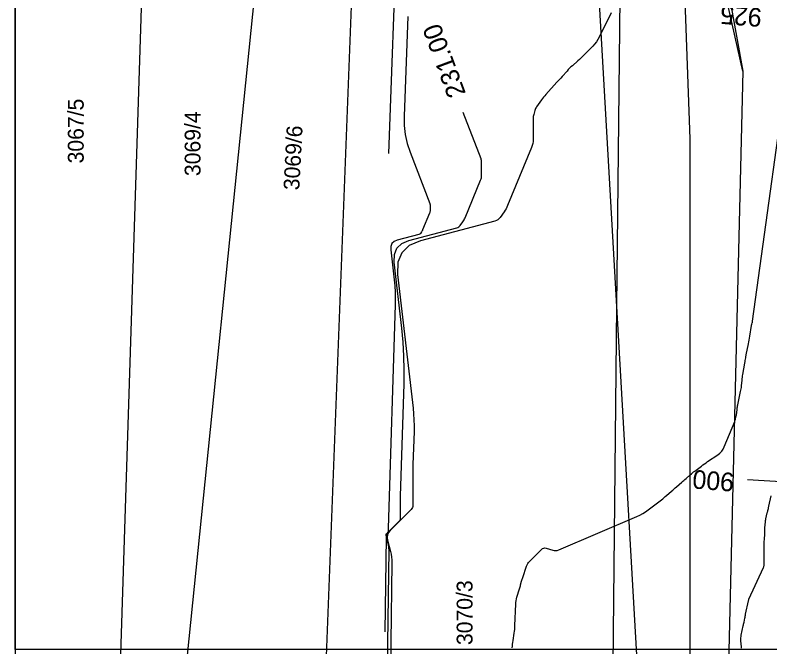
# Model space of a CAD drawing. Extents: x -534410 to -534262, y -1190162 to -1189584.
# Drawn here: x -534410.13 to -534369.58, y -1189689.33 to -1189655.39 of the extents above; entities that cross this region are included whole.
import ezdxf

# ---------------------------------------------------------------- set-up
doc = ezdxf.new("R2010")
doc.units = 0
for name, color, linetype in [('30', 7, 'Continuous'), ('31', 7, 'Continuous'), ('40', 7, 'Continuous'), ('_N_text', 7, 'Continuous'), ('_rámeček', 7, 'Continuous'), ('_rámeček_mřížka', 7, 'Continuous'), ('Hranice parcel', 7, 'Continuous'), ('Parcelní čísla', 7, 'Continuous')]:
    doc.layers.add(name, color=color, linetype=linetype)

msp = doc.modelspace()

# ---------------------------------------------------------------- linework, layer by layer
at = {"layer": '30'}
for points in [[(-534389.62, -1189650.598), (-534390.072, -1189662.819)], [(-534383.427, -1189689.383), (-534383.415, -1189689.283), (-534383.403, -1189689.183), (-534383.389, -1189689.084), (-534383.375, -1189688.984), (-534383.316, -1189688.586), (-534383.302, -1189688.487), (-534383.291, -1189688.387), (-534383.283, -1189688.287), (-534383.278, -1189688.186), (-534383.231, -1189687.038), (-534383.224, -1189686.942), (-534383.211, -1189686.847), (-534383.192, -1189686.752), (-534383.168, -1189686.659), (-534383.03, -1189686.202), (-534383.016, -1189686.152), (-534383.001, -1189686.101), (-534382.987, -1189686.051), (-534382.973, -1189686), (-534382.92, -1189685.797), (-534382.906, -1189685.746), (-534382.891, -1189685.695), (-534382.876, -1189685.645), (-534382.86, -1189685.595), (-534382.658, -1189684.99), (-534382.63, -1189684.92), (-534382.594, -1189684.854), (-534382.55, -1189684.794), (-534382.499, -1189684.739), (-534382.276, -1189684.528), (-534382.221, -1189684.475), (-534382.167, -1189684.421), (-534382.113, -1189684.367), (-534382.06, -1189684.311), (-534381.849, -1189684.089), (-534381.793, -1189684.043), (-534381.733, -1189684.017), (-534381.668, -1189684.011), (-534381.597, -1189684.024), (-534381.25, -1189684.135), (-534381.168, -1189684.153), (-534381.087, -1189684.157), (-534381.007, -1189684.146), (-534380.927, -1189684.119), (-534376.732, -1189682.324), (-534376.571, -1189682.249), (-534376.415, -1189682.164), (-534376.265, -1189682.07), (-534376.121, -1189681.967), (-534375.412, -1189681.425), (-534375.342, -1189681.371), (-534375.273, -1189681.315), (-534375.204, -1189681.257), (-534375.137, -1189681.199), (-534374.867, -1189680.961), (-534374.801, -1189680.903), (-534374.735, -1189680.845), (-534374.669, -1189680.787), (-534374.603, -1189680.729), (-534374.322, -1189680.483), (-534374.264, -1189680.432), (-534374.206, -1189680.382), (-534374.148, -1189680.331), (-534374.09, -1189680.281), (-534373.859, -1189680.079), (-534373.801, -1189680.029), (-534373.742, -1189679.98), (-534373.682, -1189679.932), (-534373.621, -1189679.885), (-534373.26, -1189679.611), (-534373.18, -1189679.55), (-534373.098, -1189679.491), (-534373.015, -1189679.432), (-534372.932, -1189679.375), (-534372.381, -1189679.005), (-534372.27, -1189678.918), (-534372.174, -1189678.818), (-534372.095, -1189678.704), (-534372.032, -1189678.578), (-534371.474, -1189677.214), (-534371.46, -1189677.178), (-534371.448, -1189677.142), (-534371.437, -1189677.106), (-534371.428, -1189677.068), (-534371.394, -1189676.919), (-534371.386, -1189676.882), (-534371.38, -1189676.844), (-534371.374, -1189676.806), (-534371.369, -1189676.769), (-534371.341, -1189676.534), (-534371.334, -1189676.482), (-534371.326, -1189676.43), (-534371.317, -1189676.379), (-534371.307, -1189676.328), (-534371.157, -1189675.615), (-534371.142, -1189675.539), (-534371.129, -1189675.462), (-534371.118, -1189675.385), (-534371.11, -1189675.308), (-534371.08, -1189674.999), (-534371.072, -1189674.922), (-534371.062, -1189674.845), (-534371.051, -1189674.768), (-534371.038, -1189674.692), (-534370.929, -1189674.091), (-534370.923, -1189674.054), (-534370.916, -1189674.017), (-534370.91, -1189673.98), (-534370.904, -1189673.942), (-534370.881, -1189673.793), (-534370.875, -1189673.756), (-534370.869, -1189673.718), (-534370.862, -1189673.681), (-534370.855, -1189673.644), (-534370.74, -1189673.05), (-534370.721, -1189672.947), (-534370.702, -1189672.844), (-534370.685, -1189672.741), (-534370.668, -1189672.638), (-534370.574, -1189672.057), (-534370.571, -1189672.038), (-534370.566, -1189672.02), (-534370.561, -1189672.002), (-534370.555, -1189671.984), (-534370.529, -1189671.912), (-534370.523, -1189671.894), (-534370.518, -1189671.876), (-534370.514, -1189671.857), (-534370.511, -1189671.838), (-534368.346, -1189656.186)], [(-534390.277, -1189701.721), (-534390.042, -1189684.12), (-534390.043, -1189684.036), (-534390.05, -1189683.951), (-534390.063, -1189683.868), (-534390.081, -1189683.785), (-534390.164, -1189683.455), (-534390.175, -1189683.375), (-534390.165, -1189683.301), (-534390.135, -1189683.232), (-534390.085, -1189683.169), (-534389.476, -1189682.56), (-534389.452, -1189682.531), (-534389.435, -1189682.5), (-534389.425, -1189682.466), (-534389.422, -1189682.43), (-534389.422, -1189682.277), (-534389.422, -1189682.201), (-534389.422, -1189682.125), (-534389.422, -1189681.932), (-534389.422, -1189681.826), (-534389.422, -1189681.651), (-534389.422, -1189681.545), (-534389.422, -1189681.387), (-534389.422, -1189681.349), (-534389.422, -1189681.311), (-534389.421, -1189681.273), (-534389.42, -1189681.235), (-534389.233, -1189675.203), (-534389.223, -1189674.453), (-534389.24, -1189673.705), (-534389.285, -1189672.958), (-534389.357, -1189672.212), (-534389.766, -1189668.662), (-534389.756, -1189668.243), (-534389.621, -1189667.91), (-534389.36, -1189667.662), (-534388.975, -1189667.5), (-534386.4, -1189666.813), (-534386.345, -1189666.793), (-534386.295, -1189666.765), (-534386.251, -1189666.729), (-534386.213, -1189666.684), (-534386.071, -1189666.489), (-534386.037, -1189666.439), (-534386.006, -1189666.387), (-534385.979, -1189666.334), (-534385.954, -1189666.279), (-534385.123, -1189664.258), (-534385.099, -1189664.191), (-534385.082, -1189664.123), (-534385.071, -1189664.053), (-534385.068, -1189663.982), (-534385.068, -1189663.597), (-534385.068, -1189663.463), (-534385.068, -1189663.284), (-534385.07, -1189663.239), (-534385.076, -1189663.195), (-534385.086, -1189663.152), (-534385.1, -1189663.11), (-534386.06, -1189660.617)]]:
    msp.add_lwpolyline(points, dxfattribs=at)
at = {"layer": '31'}
for points in [[(-534389.036, -1189655.461), (-534389.234, -1189660.821), (-534389.228, -1189661.315), (-534389.172, -1189661.802), (-534389.067, -1189662.28), (-534388.913, -1189662.749), (-534387.852, -1189665.506), (-534387.845, -1189665.525), (-534387.841, -1189665.544), (-534387.838, -1189665.564), (-534387.837, -1189665.584), (-534387.837, -1189665.745), (-534387.837, -1189665.898), (-534387.839, -1189665.93), (-534387.843, -1189665.962), (-534387.851, -1189665.992), (-534387.862, -1189666.023), (-534388.236, -1189666.932), (-534388.247, -1189666.957), (-534388.26, -1189666.981), (-534388.274, -1189667.004), (-534388.289, -1189667.027), (-534388.353, -1189667.115), (-534388.37, -1189667.135), (-534388.39, -1189667.151), (-534388.412, -1189667.164), (-534388.437, -1189667.173), (-534389.596, -1189667.482), (-534389.77, -1189667.555), (-534389.887, -1189667.667), (-534389.948, -1189667.817), (-534389.952, -1189668.005), (-534389.769, -1189669.604), (-534389.736, -1189669.94), (-534389.716, -1189670.276), (-534389.708, -1189670.613), (-534389.712, -1189670.951), (-534390.085, -1189682.943), (-534390.085, -1189682.962), (-534390.085, -1189683.066), (-534390.085, -1189683.119), (-534390.085, -1189683.144), (-534390.086, -1189683.15), (-534390.088, -1189683.156), (-534390.09, -1189683.161), (-534390.094, -1189683.166), (-534390.197, -1189683.269), (-534390.206, -1189683.28), (-534390.211, -1189683.291), (-534390.212, -1189683.304), (-534390.211, -1189683.317), (-534390.197, -1189683.373), (-534390.194, -1189683.387), (-534390.191, -1189683.401), (-534390.19, -1189683.415), (-534390.19, -1189683.43), (-534390.258, -1189688.509)], [(-534378.108, -1189655.268), (-534378.751, -1189656.572), (-534378.823, -1189656.705), (-534378.905, -1189656.83), (-534378.997, -1189656.948), (-534379.1, -1189657.059), (-534379.6, -1189657.56), (-534379.672, -1189657.631), (-534379.745, -1189657.701), (-534379.819, -1189657.77), (-534379.894, -1189657.838), (-534380.195, -1189658.107), (-534380.269, -1189658.176), (-534380.341, -1189658.246), (-534380.412, -1189658.319), (-534380.48, -1189658.393), (-534380.75, -1189658.694), (-534380.817, -1189658.769), (-534380.885, -1189658.844), (-534380.952, -1189658.92), (-534381.02, -1189658.995), (-534381.618, -1189659.659), (-534381.68, -1189659.73), (-534381.739, -1189659.802), (-534381.797, -1189659.875), (-534381.853, -1189659.95), (-534382.116, -1189660.313), (-534382.147, -1189660.36), (-534382.173, -1189660.41), (-534382.195, -1189660.461), (-534382.212, -1189660.515), (-534382.27, -1189660.735), (-534382.283, -1189660.79), (-534382.292, -1189660.845), (-534382.297, -1189660.902), (-534382.299, -1189660.958), (-534382.299, -1189661.331), (-534382.299, -1189661.47), (-534382.299, -1189661.539), (-534382.299, -1189662.067), (-534382.304, -1189662.177), (-534382.32, -1189662.284), (-534382.346, -1189662.39), (-534382.383, -1189662.494), (-534383.672, -1189665.626), (-534383.71, -1189665.711), (-534383.753, -1189665.793), (-534383.8, -1189665.873), (-534383.853, -1189665.95), (-534384.073, -1189666.254), (-534384.132, -1189666.323), (-534384.2, -1189666.379), (-534384.277, -1189666.423), (-534384.363, -1189666.453), (-534388.353, -1189667.518), (-534388.951, -1189667.769), (-534389.354, -1189668.153), (-534389.564, -1189668.67), (-534389.579, -1189669.318), (-534388.753, -1189676.5), (-534388.722, -1189676.816), (-534388.703, -1189677.132), (-534388.696, -1189677.448), (-534388.7, -1189677.765), (-534388.755, -1189679.527), (-534388.757, -1189679.597), (-534388.758, -1189679.667), (-534388.759, -1189679.736), (-534388.759, -1189679.806), (-534388.759, -1189680.095), (-534388.759, -1189680.224), (-534388.759, -1189680.353), (-534388.759, -1189680.61), (-534388.759, -1189680.739), (-534388.759, -1189680.868), (-534388.759, -1189681.157), (-534388.759, -1189681.227), (-534388.759, -1189681.297), (-534388.759, -1189681.366), (-534388.759, -1189681.436), (-534388.759, -1189681.715), (-534388.765, -1189681.782), (-534388.783, -1189681.844), (-534388.814, -1189681.901), (-534388.857, -1189681.953), (-534389.973, -1189683.069), (-534390.065, -1189683.184), (-534390.12, -1189683.31), (-534390.137, -1189683.446), (-534390.118, -1189683.592), (-534389.965, -1189684.197), (-534389.932, -1189684.348), (-534389.909, -1189684.501), (-534389.896, -1189684.656), (-534389.893, -1189684.811), (-534389.95, -1189689.079), (-534389.953, -1189689.842)], [(-534371.113, -1189689.402), (-534371.118, -1189689.322), (-534371.142, -1189689.004), (-534371.145, -1189688.924), (-534371.143, -1189688.845), (-534371.135, -1189688.767), (-534371.121, -1189688.688), (-534371.018, -1189688.202), (-534371.007, -1189688.149), (-534370.996, -1189688.097), (-534370.985, -1189688.045), (-534370.974, -1189687.992), (-534370.931, -1189687.782), (-534370.921, -1189687.73), (-534370.91, -1189687.678), (-534370.899, -1189687.625), (-534370.887, -1189687.573), (-534370.734, -1189686.861), (-534370.73, -1189686.844), (-534370.727, -1189686.828), (-534370.72, -1189686.794), (-534370.719, -1189686.785), (-534370.716, -1189686.777), (-534370.713, -1189686.769), (-534370.71, -1189686.761), (-534369.927, -1189685.056), (-534369.915, -1189685.024), (-534369.906, -1189684.991), (-534369.9, -1189684.958), (-534369.898, -1189684.923), (-534369.898, -1189684.68), (-534369.898, -1189684.075), (-534369.898, -1189683.971), (-534369.898, -1189683.832), (-534369.898, -1189683.797), (-534369.897, -1189683.762), (-534369.894, -1189683.727), (-534369.891, -1189683.693), (-534369.875, -1189683.53), (-534369.871, -1189683.491), (-534369.869, -1189683.452), (-534369.867, -1189683.414), (-534369.865, -1189683.375), (-534369.854, -1189682.937), (-534369.853, -1189682.896), (-534369.85, -1189682.856), (-534369.847, -1189682.815), (-534369.843, -1189682.774), (-534369.823, -1189682.612), (-534369.818, -1189682.572), (-534369.812, -1189682.532), (-534369.804, -1189682.491), (-534369.796, -1189682.452), (-534369.722, -1189682.123), (-534369.715, -1189682.093), (-534369.709, -1189682.064), (-534369.702, -1189682.034), (-534369.695, -1189682.004), (-534369.667, -1189681.884), (-534369.66, -1189681.854), (-534369.653, -1189681.824), (-534369.646, -1189681.794), (-534369.64, -1189681.764), (-534369.521, -1189681.219)]]:
    msp.add_lwpolyline(points, dxfattribs=at)
at = {"layer": '_N_text'}
msp.add_lwpolyline([(-534358.817, -1189681.064), (-534370.796, -1189680.351)], dxfattribs=at)
at = {"layer": '_rámeček'}
msp.add_line((-534410.126, -1189584.47), (-534410.126, -1190161.97), dxfattribs=at)
msp.add_lwpolyline([(-534410.126, -1189584.47), (-534261.626, -1189584.47), (-534261.626, -1189689.47), (-534410.126, -1189689.47)], close=True, dxfattribs=at)
at = {"layer": '_rámeček_mřížka'}
msp.add_line((-534410.126, -1189584.47), (-534410.126, -1190161.97), dxfattribs=at)
at = {"layer": 'Hranice parcel'}
for p, q in [((-534404.82, -1189701), (-534402.64, -1189633.7)), ((-534394.19, -1189710.57), (-534391.41, -1189637.73)), ((-534374.52, -1189639.2), (-534371.04, -1189658.4)), ((-534377.8, -1189671.05), (-534379.42, -1189642.82)), ((-534377.8, -1189671.05), (-534377.5, -1189643.64)), ((-534371.04, -1189658.4), (-534373.49, -1189759.21)), ((-534378.67, -1189750.28), (-534377.8, -1189671.05))]:
    msp.add_line(p, q, dxfattribs=at)
for points in [[(-534402.1, -1189701.89), (-534396.03, -1189642.33), (-534395.58, -1189636.23)], [(-534373.49, -1189759.21), (-534375.27, -1189742.09), (-534373.87, -1189702.99), (-534373.87, -1189662.03), (-534374.42, -1189646.7)], [(-534371.04, -1189658.4), (-534373.46, -1189647.66), (-534374.42, -1189646.7)], [(-534378.12, -1189750.26), (-534378.12, -1189746.17), (-534376.49, -1189693.82), (-534377.8, -1189671.05)]]:
    msp.add_lwpolyline(points, dxfattribs=at)

# ---------------------------------------------------------------- texts
at = {"layer": '40'}
msp.add_text('231.00', height=1, rotation=110.3229, dxfattribs=at).set_placement((-534385.903, -1189659.601))
at = {"layer": '_N_text'}
for s, p in [('925', (-534369.985, -1189655.037)), ('900', (-534371.471, -1189679.993))]:
    msp.add_text(s, height=1, rotation=175.3668, dxfattribs=at).set_placement(p)
at = {"layer": 'Parcelní čísla'}
for s, rotation, p in [('3067/5', 90, (-534406.442, -1189663.357)), ('3069/4', 90, (-534400.167, -1189664.038)), ('3069/6', 87, (-534394.864, -1189664.813)), ('3070/3', 90, (-534385.558, -1189689.227))]:
    msp.add_text(s, height=0.85, rotation=rotation, dxfattribs=at).set_placement(p)

doc.saveas('drawing.dxf')
